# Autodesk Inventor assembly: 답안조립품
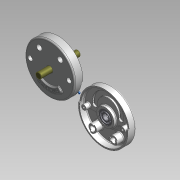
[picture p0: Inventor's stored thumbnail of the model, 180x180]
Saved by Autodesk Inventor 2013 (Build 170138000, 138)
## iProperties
Created: 2015-04
Part Number: 답안조립품
Document SubType Name: 조립품
Designer: Administrator
Author: Administrator
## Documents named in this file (10)
- C:\Users\Administrator\Desktop\450406V1002\답안조립품.iam
- C:\Users\Administrator\Desktop\450406V1002\본체.ipt
- C:\Users\Administrator\Desktop\450406V1002\M 10 x 35.ipt
- C:\Users\Administrator\Desktop\450406V1002\덮개.ipt
- C:\Users\Administrator\Desktop\450406V1002\멈춤링.ipt
- C:\Users\Administrator\Desktop\450406V1002\베어링62_22.ipt
- C:\Users\Administrator\Desktop\450406V1002\슬라이더.ipt
- C:\Users\Administrator\Desktop\450406V1002\슬라이더2.ipt
- C:\Users\Administrator\Desktop\450406V1002\축.ipt
- C:\Users\Administrator\Desktop\450406V1002\평행핀.ipt
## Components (1 placed, 1 different names)
1. M 10 x 35:1
